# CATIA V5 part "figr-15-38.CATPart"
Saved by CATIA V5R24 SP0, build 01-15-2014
Part number: Part1
Bounding box of the stored display mesh (mm): x -63.331 to 69.186, y -39.139 to 39.139, z 0 to 69.963
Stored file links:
  D:\KAVITA\CATIA V5-6R2014 Project_ Kavita\CATIA V5-6R2014_partfiles\Partfiles\c15_catia_v5-6r2014_prt\figr-15-38.CATPart
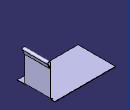
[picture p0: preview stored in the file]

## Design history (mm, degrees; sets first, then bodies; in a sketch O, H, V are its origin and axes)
SheetMetalParameters1: Thickness 1, BendRadius 2, KFactor 0.400515 {= log(min(100,max(20*SheetMetalParameters1.BendRadius,SheetMetalParameters1.Thickness)/SheetMetalParameters1.Thickness))/log(100)/2}, ReliefRadialLength 1, ReliefAxialLength 2, MinimumBendRadius 0
Body1 (main body)
  Sketch1 on xy-plane, origin (0, 0, 0), H (1, 0, 0), V (0, 1, 0)
    line L1 (-63.3311, 39.1393) -> (63.3311, 39.1393)
    line L2 (63.3311, 39.1393) -> (63.3311, -39.1393)
    line L3 (63.3311, -39.1393) -> (-63.3311, -39.1393)
    line L4 (-63.3311, -39.1393) -> (-63.3311, 39.1393)
    horizontal: L1 H, L3 H
    vertical: L2 V, L4 V
    symmetry: L4 L2 V, L1 L3 H
  Wall1: Thickness 1, Profile Sketch1
  d_NewWallOnEdge1: NewWallOnEdge_Edge edge [face of Wall1 | face of Wall1], NewWallOnEdge_Length 67, NewWallOnEdge_HeightLimitOffset 0, NewWallOnEdge_WidthOffset1 -16, NewWallOnEdge_WidthOffset2 -9, NewWallOnEdge_Angle 90, NewWallOnEdge_BendRadiusValue 2 {= SheetMetalParameters1.BendRadius}, NewWallOnEdge_BendTable SheetMetalParameters1, KFacteur 0.400515 {= log(min(100,max(20*d_NewWallOnEdge1.Radius,SheetMetalParameters1.Thickness)/SheetMetalParameters1.Thickness))/log(100)/2}
  Flange1: Angle 22.6199 {= 2*atan(Flange1.Radius/Flange1.Length)}, Length 10, Radius 2, KFacteur 0.400515 {= log(min(100,max(20*Flange1.Radius,SheetMetalParameters1.Thickness)/SheetMetalParameters1.Thickness))/log(100)/2}, Guide edge [face of d_NewWallOnEdge1 | face of d_NewWallOnEdge1]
